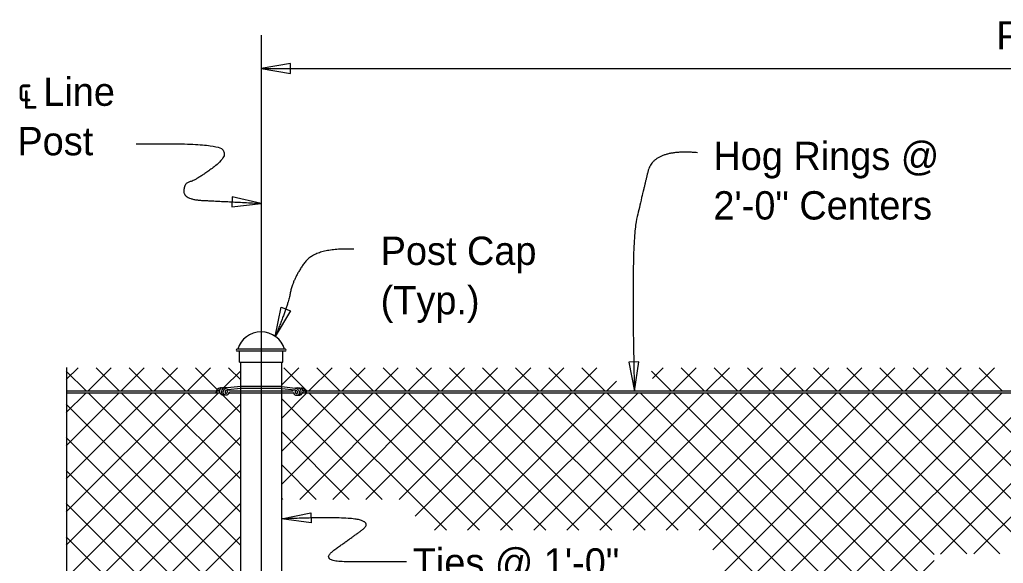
# Model space of a CAD drawing. Extents: x 0.5 to 39.7, y 0.9 to 25.6.
# Drawn here: x 0.49 to 7.49, y 21.74 to 25.61 of the extents above; entities that cross this region are included whole.
import ezdxf

# ---------------------------------------------------------------- set-up
doc = ezdxf.new("R2010")
doc.units = 0
for name, color, linetype in [('CL_Major', 7, 'Continuous'), ('Dimension', 7, 'Continuous'), ('Miscellaneous', 7, 'Continuous'), ('SteelMisc', 7, 'Continuous'), ('SteelMisc_h', 7, 'Continuous'), ('TextStructures', 7, 'Continuous')]:
    doc.layers.add(name, color=color, linetype=linetype)

msp = doc.modelspace()

# ---------------------------------------------------------------- linework, layer by layer
at = {"layer": 'CL_Major'}
msp.add_line((2.2062, 25.5043), (2.2062, 14.6639), dxfattribs=at)
at = {"layer": 'Dimension'}
msp.add_line((2.2062, 25.2672), (22.2062, 25.2672), dxfattribs=at)
for points in [[(2.2062, 25.2672), (2.4145, 25.2319), (2.4145, 25.3025)], [(2.2062, 24.3062), (2.0002, 24.3528), (1.9964, 24.2823)], [(2.3061, 23.3596), (2.3482, 23.5666), (2.414, 23.5412)], [(4.8623, 22.9695), (4.8931, 23.1785), (4.8225, 23.177)], [(2.3519, 22.0601), (2.5585, 22.1039), (2.5614, 22.0334)]]:
    msp.add_lwpolyline(points, close=True, dxfattribs=at)
msp.add_lwpolyline([(0.8194, 23.1382), (0.8194, 21.1819), (0.9227, 21.1819), (0.8194, 21.1369), (0.716, 21.0919), (0.8194, 21.0919), (0.8194, 20.1983)], dxfattribs=at)
for points in [[(1.3166, 24.7299), (1.8624, 24.7397), (1.9848, 24.6508), (1.7406, 24.4695), (1.6558, 24.4512), (1.6558, 24.3333), (1.9338, 24.321), (2.2061, 24.3061)], [(5.3115, 24.667), (4.9982, 24.6953), (4.9198, 24.3731), (4.8367, 24.0148), (4.8622, 22.9695)], [(2.8646, 23.9801), (2.5898, 23.9929), (2.4301, 23.7626), (2.3965, 23.5753), (2.3061, 23.3596)], [(3.2402, 21.7554), (3.0279, 21.7554), (2.6079, 21.7554), (2.8581, 21.9325), (2.9953, 22.0352), (2.7847, 22.0777), (2.352, 22.06)]]:
    msp.add_open_spline(points, degree=2, dxfattribs=at)
at = {"layer": 'Miscellaneous'}
for p, q in [((0.9027, 23.1361), (0.8192, 23.0527)), ((0.9619, 22.9695), (0.8192, 23.1121)), ((1.1384, 23.1361), (0.9717, 22.9695)), ((1.1976, 22.9695), (1.0309, 23.1361)), ((1.3741, 23.1361), (1.2074, 22.9695)), ((1.4333, 22.9695), (1.2666, 23.1361)), ((1.6098, 23.1361), (1.4431, 22.9695)), ((1.669, 22.9695), (1.5023, 23.1361)), ((1.8455, 23.1361), (1.6788, 22.9695)), ((1.8932, 22.981), (1.738, 23.1361)), ((2.0603, 23.1153), (1.9381, 22.993)), ((2.0603, 23.0495), (1.9737, 23.1361)), ((2.4746, 23.1361), (2.352, 23.0136)), ((2.5338, 22.9695), (2.3671, 23.1361)), ((2.7103, 23.1361), (2.5436, 22.9695)), ((2.7695, 22.9695), (2.6028, 23.1361)), ((2.946, 23.1361), (2.7793, 22.9695)), ((3.0052, 22.9695), (2.8385, 23.1361)), ((3.1817, 23.1361), (3.015, 22.9695)), ((3.2409, 22.9695), (3.0742, 23.1361)), ((3.4174, 23.1361), (3.2507, 22.9695)), ((3.4766, 22.9695), (3.3099, 23.1361)), ((3.6531, 23.1361), (3.4864, 22.9695)), ((3.7123, 22.9695), (3.5456, 23.1361)), ((3.8888, 23.1361), (3.7221, 22.9695)), ((3.948, 22.9695), (3.7813, 23.1361)), ((4.1245, 23.1361), (3.9578, 22.9695)), ((4.1837, 22.9695), (4.017, 23.1361)), ((4.3602, 23.1361), (4.1935, 22.9695)), ((4.4194, 22.9695), (4.2527, 23.1361)), ((4.5959, 23.1361), (4.4292, 22.9695)), ((4.6551, 22.9695), (4.4884, 23.1361)), ((5.1265, 22.9695), (4.9846, 23.1113)), ((5.0673, 23.1361), (4.991, 23.0599)), ((5.303, 23.1361), (5.1363, 22.9695)), ((5.3622, 22.9695), (5.1955, 23.1361)), ((5.5387, 23.1361), (5.372, 22.9695)), ((5.5979, 22.9695), (5.4312, 23.1361)), ((5.7744, 23.1361), (5.6077, 22.9695)), ((5.8336, 22.9695), (5.6669, 23.1361)), ((6.0101, 23.1361), (5.8434, 22.9695)), ((6.0693, 22.9695), (5.9026, 23.1361)), ((6.2458, 23.1361), (6.0791, 22.9695)), ((6.305, 22.9695), (6.1383, 23.1361)), ((6.4815, 23.1361), (6.3148, 22.9695)), ((6.5407, 22.9695), (6.374, 23.1361)), ((6.7172, 23.1361), (6.5505, 22.9695)), ((6.7764, 22.9695), (6.6097, 23.1361)), ((6.9529, 23.1361), (6.7862, 22.9695)), ((7.0121, 22.9695), (6.8455, 23.1361)), ((7.1886, 23.1361), (7.0219, 22.9695)), ((7.2478, 22.9695), (7.0812, 23.1361)), ((7.4243, 23.1361), (7.2576, 22.9695)), ((7.4835, 22.9695), (7.3169, 23.1361)), ((4.7358, 23.0403), (4.6649, 22.9695)), ((1.9047, 22.9695), (1.9002, 22.9739)), ((4.8908, 22.9695), (4.8908, 22.9695)), ((1.8998, 22.9547), (0.8192, 21.8742)), ((1.6641, 22.9547), (0.8192, 22.1099)), ((1.1927, 22.9547), (0.8192, 22.5813)), ((1.4284, 22.9547), (0.8192, 22.3456)), ((0.957, 22.9547), (0.8192, 22.817)), ((2.0603, 21.871), (0.9766, 22.9547)), ((2.0559, 22.1112), (1.2123, 22.9547)), ((2.0603, 22.3424), (1.448, 22.9547)), ((2.0603, 22.5781), (1.6837, 22.9547)), ((2.0603, 22.8138), (1.9308, 22.9433)), ((3.0002, 22.9547), (2.352, 22.3064)), ((2.7645, 22.9547), (2.352, 22.5421)), ((2.5288, 22.9547), (2.352, 22.7779)), ((3.0682, 22.1994), (2.352, 22.9155)), ((3.2359, 22.9547), (2.4806, 22.1994)), ((3.5244, 21.9789), (2.5485, 22.9547)), ((3.4716, 22.9547), (2.7163, 22.1994)), ((3.7601, 21.9789), (2.7842, 22.9547)), ((3.7073, 22.9547), (2.952, 22.1994)), ((3.9958, 21.9789), (3.0199, 22.9547)), ((3.943, 22.9547), (3.1877, 22.1994)), ((4.2315, 21.9789), (3.2556, 22.9547)), ((4.1788, 22.9547), (3.303, 22.0789)), ((4.4145, 22.9547), (3.4386, 21.9789)), ((4.4672, 21.9789), (3.4913, 22.9547)), ((4.6502, 22.9547), (3.6743, 21.9789)), ((4.7029, 21.9789), (3.727, 22.9547)), ((4.8859, 22.9547), (3.91, 21.9789)), ((4.9386, 21.9789), (3.9627, 22.9547)), ((5.1216, 22.9547), (4.1457, 21.9789)), ((5.1743, 21.9789), (4.1984, 22.9547)), ((7.2429, 22.9547), (4.2774, 19.9892)), ((5.3573, 22.9547), (4.3814, 21.9789)), ((7.2492, 20.1396), (4.4341, 22.9547)), ((7.4786, 22.9547), (4.5131, 19.9892)), ((5.593, 22.9547), (4.6171, 21.9789)), ((7.4034, 20.2211), (4.6698, 22.9547)), ((7.7143, 22.9547), (4.7488, 19.9892)), ((5.8287, 22.9547), (4.8528, 21.9789)), ((7.5576, 20.3026), (4.9055, 22.9547)), ((7.95, 22.9547), (4.9845, 19.9892)), ((6.0644, 22.9547), (5.0885, 21.9789)), ((7.7118, 20.3841), (5.1412, 22.9547)), ((6.3001, 22.9547), (5.3242, 21.9789)), ((6.9957, 21.336), (5.377, 22.9547)), ((6.5358, 22.9547), (5.4205, 21.8394)), ((6.7715, 22.9547), (5.4205, 21.6037)), ((7.0072, 22.9547), (5.5678, 21.5153)), ((6.9957, 21.5717), (5.6127, 22.9547)), ((6.9957, 21.8074), (5.8484, 22.9547)), ((7.2277, 21.811), (6.0841, 22.9547)), ((7.4634, 21.811), (6.3198, 22.9547)), ((7.6991, 21.811), (6.5555, 22.9547)), ((7.9348, 21.811), (6.7912, 22.9547)), ((8.1705, 21.811), (7.0269, 22.9547)), ((8.1857, 22.9547), (7.041, 21.81)), ((8.4062, 21.811), (7.2626, 22.9547)), ((8.4214, 22.9547), (7.2777, 21.811)), ((2.0603, 22.8796), (0.8192, 21.6385)), ((2.0603, 21.6353), (0.8192, 22.8764)), ((2.0603, 22.6439), (0.8192, 21.4028)), ((2.0603, 21.3996), (0.8192, 22.6407)), ((2.8325, 22.1994), (2.352, 22.6798)), ((2.0603, 22.4082), (0.7982, 21.146)), ((2.0603, 21.1639), (0.8192, 22.405)), ((2.5968, 22.1994), (2.352, 22.4441)), ((2.3611, 22.1994), (2.352, 22.2084)), ((2.0603, 22.1725), (0.8192, 20.9314)), ((2.0603, 20.9282), (0.8192, 22.1693)), ((2.0603, 21.9368), (0.8192, 20.6957)), ((2.0603, 20.6925), (0.8192, 21.9336)), ((6.9957, 21.7647), (5.2202, 19.9892))]:
    msp.add_line(p, q, dxfattribs=at)
at = {"layer": 'SteelMisc'}
for p, q in [((2.3786, 23.2681), (2.034, 23.2681)), ((2.034, 23.2559), (2.3786, 23.2559)), ((2.0522, 23.1761), (2.0522, 23.2559)), ((2.3603, 23.1761), (2.3603, 23.2559)), ((2.0522, 23.1761), (2.3603, 23.1761)), ((2.0603, 17.5309), (2.0603, 23.1761)), ((2.352, 17.5309), (2.352, 23.1761)), ((1.8859, 22.9695), (0.8192, 22.9695)), ((1.9096, 22.9695), (1.8943, 22.9695)), ((2.0608, 23.0038), (1.9665, 22.9926)), ((2.0608, 22.9892), (1.9687, 22.9798)), ((2.0603, 22.9695), (1.9799, 22.9695)), ((2.352, 23.0021), (2.0608, 23.0038)), ((2.352, 22.9876), (2.0608, 22.9892)), ((2.352, 23.0021), (2.4469, 22.991)), ((2.352, 22.9876), (2.4446, 22.978)), ((2.4342, 22.9695), (2.352, 22.9695)), ((2.5172, 22.9695), (2.5041, 22.9695)), ((11.923, 22.9695), (2.5271, 22.9695)), ((1.9145, 22.9547), (0.8192, 22.9547)), ((2.0603, 22.9547), (1.9773, 22.9547)), ((2.4356, 22.9547), (2.352, 22.9547)), ((11.9243, 22.9547), (2.5005, 22.9547))]:
    msp.add_line(p, q, dxfattribs=at)
for centre, start, end in [((2.034, 23.2618), 91.1647, 268.8353), ((2.3783, 23.2618), 271.1647, 88.8353)]:
    msp.add_arc(centre, 0.00613, start, end, dxfattribs=at)
for centre, major_axis, ratio, start_param, end_param in [((2.2055, 23.227), (-0.1711, 0), 0.957868, 3.394611, 6.030583), ((1.9209, 22.957), (0.0373, 0), 0.957868, 1.486836, 3.108042), ((1.942, 22.9173), (-0.0724, 0), 0.957868, 5.162149, 5.652106), ((1.9345, 22.9689), (-0.0249, 0), 0.957868, 6.009018, 7.089857), ((1.9333, 22.9714), (0.023, 0), 0.957868, 1.29026, 2.970541), ((1.9521, 22.9661), (0.0295, 0), 0.957868, 1.220941, 4.039556), ((1.9656, 22.9678), (-0.0303, -0.0108), 0.724765, 4.35367, 6.324556), ((1.9623, 22.9638), (-0.0139, 0), 0.957868, 5.22362, 6.905413), ((1.9706, 22.9549), (-0.0259, 0), 0.957868, 4.777514, 5.62749), ((1.9549, 22.9672), (0.0119, 0), 0.957868, 5.725876, 7.416677), ((1.9551, 22.966), (0.0251, 0), 0.957868, 5.531357, 6.227833), ((1.9551, 22.966), (0.0251, 0), 0.957868, 0.407687, 0.609214), ((2.4586, 22.9642), (-0.0251, 0), 0.957868, 5.673972, 5.875498), ((2.4431, 22.9532), (0.0259, 0), 0.957868, 0.655696, 1.505671), ((2.4482, 22.9661), (0.0303, -0.0108), 0.724765, 6.241815, 8.212701), ((2.4589, 22.9654), (-0.0119, 0), 0.957868, 5.149694, 6.840495), ((2.4617, 22.9643), (-0.0295, 0), 0.957868, 2.243629, 5.062245), ((2.4515, 22.962), (0.0139, 0), 0.957868, 5.660958, 7.342751), ((2.4804, 22.9697), (-0.023, 0), 0.957868, 3.312645, 4.992926), ((2.4929, 22.9552), (-0.0373, 0), 0.957868, 3.175144, 4.79635), ((2.4793, 22.9671), (0.0249, 0), 0.957868, 5.476514, 6.557353), ((2.4718, 22.9155), (0.0724, 0), 0.957868, 0.631079, 1.121037), ((1.9359, 22.9649), (0.0231, 0), 0.957868, 3.779554, 4.879821), ((1.942, 22.9592), (0.0206, -0.0021), 0.798607, 4.32653, 5.220153), ((1.9554, 22.9592), (0.0206, -0.0021), 0.798607, 3.333154, 5.220153), ((1.9566, 22.9614), (-0.00795, 0), 0.957868, 6.140374, 9.314262), ((1.9481, 22.978), (0.0391, 0), 0.957868, 5.082588, 5.41974), ((1.9549, 22.9672), (0.0119, 0), 0.957868, 5.639684, 5.723117), ((2.4586, 22.9642), (-0.0251, 0), 0.957868, 0.055352, 0.751829), ((2.4657, 22.9762), (-0.0391, 0), 0.957868, 0.863445, 1.200597), ((2.4589, 22.9654), (-0.0119, 0), 0.957868, 0.560069, 0.643501), ((2.4572, 22.9596), (0.00795, 0), 0.957868, 3.252108, 6.425997), ((2.4583, 22.9575), (-0.0206, -0.0021), 0.798607, 1.063032, 2.950031), ((2.4718, 22.9575), (-0.0206, -0.0021), 0.798607, 1.063032, 1.956656), ((2.4779, 22.9631), (-0.0231, 0), 0.957868, 1.403365, 2.503632)]:
    msp.add_ellipse(centre, major_axis=major_axis, ratio=ratio, start_param=start_param, end_param=end_param, dxfattribs=at)
at = {"layer": 'SteelMisc_h'}
for p, q in [((2.352, 22.9695), (2.0603, 22.9695)), ((2.352, 22.9547), (2.0603, 22.9547))]:
    msp.add_line(p, q, dxfattribs=at)

# ---------------------------------------------------------------- texts
at = {"layer": 'Dimension'}
for s, p in [('℄ Line ', (0.4712, 25.0009)), ('Post', (0.4712, 24.6489)), ('Hog Rings @ ', (5.4249, 24.5436)), ('2\'-0" Centers', (5.4249, 24.1916)), ('Post Cap ', (3.0566, 23.8683)), ('(Typ.)', (3.0566, 23.5163))]:
    msp.add_text(s, height=0.2016, dxfattribs=at).set_placement(p)
at = {"layer": 'TextStructures'}
for s, p in [('Pull Post Assembly (required at maximum intervals of 500\'-0")', (7.4383, 25.402)), ('Ties @ 1\'-0" ', (3.285, 21.6493))]:
    msp.add_text(s, height=0.2016, dxfattribs=at).set_placement(p)

doc.saveas('drawing.dxf')
